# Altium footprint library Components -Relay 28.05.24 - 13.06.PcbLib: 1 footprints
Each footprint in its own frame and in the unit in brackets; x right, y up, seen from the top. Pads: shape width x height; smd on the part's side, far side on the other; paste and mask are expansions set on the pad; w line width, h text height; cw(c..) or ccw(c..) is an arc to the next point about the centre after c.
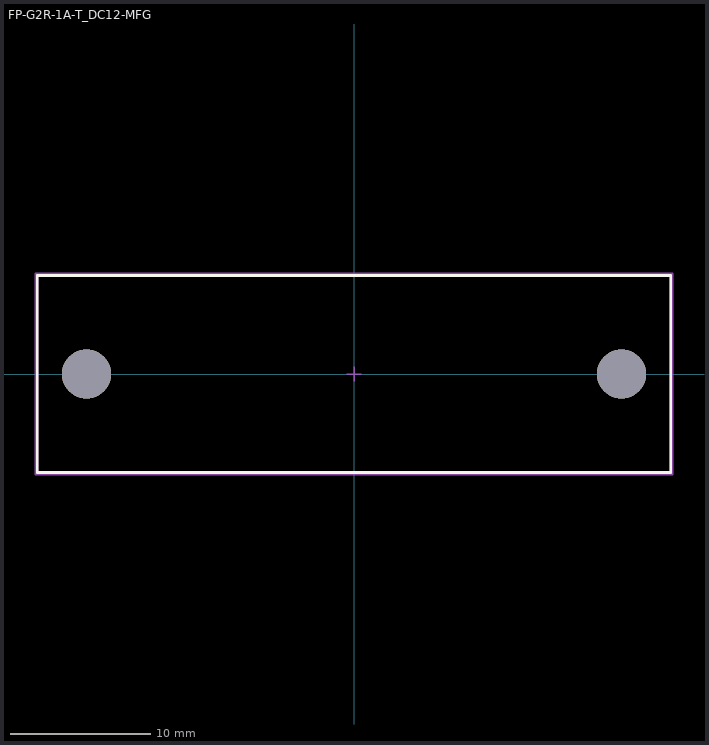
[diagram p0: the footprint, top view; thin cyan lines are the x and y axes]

## FP-G2R-1A-T_DC12-MFG [mm]
pads (2):
  round 3.5 hole 3.5 unplated paste-2539.97 mask+0: ""(-19,0) ""(19,0)
Top Overlay:
  lines w0.2: -22.5,-7 -22.5,7 22.5,7 22.5,-7 -22.5,-7
Top Assembly:
  lines w0.2: -22.6,-7.1 -22.6,7.1 22.6,7.1 22.6,-7.1 -22.6,-7.1
  text ".Designator" at 0,-0.001 h1
Top 3D Body:
  lines w0.2: -22.5,-7 -22.5,7 22.5,7 22.5,-7 -22.5,-7
Top Courtyard:
  lines w0.2: -22.6,-7.1 -22.6,7.1 22.6,7.1 22.6,-7.1 -22.6,-7.1
Top Component Center:
  lines w0.1: -0.5,0 0.5,0 ; 0,-0.5 0,0.5
3D body "Relay_Omron_G2R-1A-T_DC12_eec.STEP": height 0.25, standoff 0, extent -22.6,-7.1 22.6,7.1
